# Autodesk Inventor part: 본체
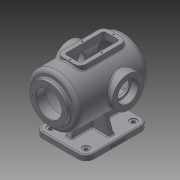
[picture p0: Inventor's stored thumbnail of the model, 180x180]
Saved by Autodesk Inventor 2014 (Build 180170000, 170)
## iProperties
Created: 2021-11
Part Number: 본체
Material: 일반
Document SubType Name: Modeling
Designer: kb542-02
Density: 1 g/cm^3
Appearance: 기본값
Mass: 1311.57 g
Surface Area: 2406 cm^2
Volume: 1311.57 cm^3
Author: kb542-02
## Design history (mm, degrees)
sketch "스케치1"
  geometry: L1 (0, 0)-(210, 0); L2 (0, 32.5)-(0, 47.5); L3 (0, 47.5)-(10, 47.5); L4 (10, 47.5)-(10, 65); L5 (10, 65)-(185.993, 65); L6 (0, 32.5)-(25, 32.5); L7 (25, 32.5)-(25, 55); L8 (25, 55)-(181.239, 55); L9 (200, 0)-(210, 0); A1 r 100 centre (110, 0) between (210, 0) and (185.993, 65); A2 r 90 centre (110, 0) between (200, 0) and (181.239, 55)
  constraints: 18 end point, 4 point on circle, 3 parallel, 3 perpendicular, 2 centre point, 2 horizontal, 1 coincident, 1 collinear, 1 horizontal alignment, 1 point on line, 1 vertical alignment
  dimensions: "d0" = 100 radius of A1; "d1" = 65 diameter of L6 L1; "d2" = 95 diameter of L3 L1; "d3" = 130 diameter of L5 L1; "d4" = 110 diameter of L8 L1; "d5" = 210 distance from line of L1.end L2; "d7" = 25 distance between parallel lines of L7 L2; "d8" = 10 radial gap between concentric circles of A1 A2; "d137" = 10 distance between parallel lines of L4 L2
revolve "회전1" sketch "스케치1" stored, may be unused: angle "d6" = 90 deg
node "작업 평면1"
sketch "스케치2"
  geometry: L1 (30, 65)-(190, 65); L2 (190, 65)-(190, -65); L3 (190, -65)-(30, -65); L4 (30, -65)-(30, 65); L5 (0, -47.5)-(0, 47.5) reference; 3 further points
  constraints: 8 end point, 2 midpoint, 2 parallel, 1 horizontal, 1 horizontal alignment, 1 perpendicular
  dimensions: "d10" = 130 distance between parallel lines of L3 L1; "d11" = 160 distance between parallel lines of L4 L2; "d12" = 30 distance between parallel lines of L5 L4
extrude "돌출1" join sketch "스케치2" distance "d13" = 14; taper "d14" = 0 deg
fillet "모깎기1" dims "d15" = 20
sketch "스케치3"
  geometry: A1 r 20 centre (170, 45) between (190, 45) and (170, 65) reference; A2 r 20 centre (50, 45) between (50, 65) and (30, 45) reference; A3 r 20 centre (50, -45) between (30, -45) and (50, -65) reference; A4 r 20 centre (170, -45) between (170, -65) and (190, -45) reference; 5 further points
  constraints: 4 coincident
hole "구멍1" sketch "스케치3" at (50, 45), (170, 45), (170, -45), (50, -45) diameter "d16" = 9; stored, may be unused: countersink angle "d20" = 90 deg, drill point angle "d22" = 118 deg; dims "d17" = 6, "d18" = 18, "d19" = 2, "d21" = 8
sketch "스케치4"
  geometry: L1 (170, 65)-(50, 65) reference; L2 (190, -45)-(190, 45) reference; L3 (103, 50)-(117, 50); L4 (117, 50)-(117, -50); L5 (117, -50)-(103, -50); L6 (103, -50)-(103, 50); L7 (50, 7)-(170, 7); L8 (170, 7)-(170, -7); L9 (170, -7)-(50, -7); L10 (50, -7)-(50, 7); 7 further points
  constraints: 16 end point, 6 midpoint, 4 parallel, 2 horizontal, 2 horizontal alignment, 2 perpendicular, 2 vertical alignment
  dimensions: "d23" = 14 distance between parallel lines of L4 L6; "d24" = 14 distance between parallel lines of L9 L7; "d25" = 120 distance between parallel lines of L8 L10; "d26" = 100 distance between parallel lines of L5 L3
extrude "돌출3" join sketch "스케치4" stored distance "d29" = 14; taper "d30" = 0 deg
feature "면 기울기1" dims angle "d31" = 20 deg
sketch "스케치8" dims "d60" = 80
  geometry: L1 (0, 0)-(0, 40); C1 r 47.5 at (0, 0) reference; 1 further point
  constraints: 2 coincident, 2 end point, 1 vertical, 1 vertical alignment, 2 other
hole "구멍4" sketch "스케치8" at (0, 40) diameter "d61" = 3.242; stored, may be unused: countersink angle "d65" = 90 deg, drill point angle "d67" = 118 deg; dims "d62" = 11, "d63" = 52, "d64" = 18, "d66" = 13
node "작업 평면3"
sketch "스케치9"
  geometry: L1 (50, 30)-(170, 30); L2 (170, 30)-(170, -30); L3 (170, -30)-(50, -30); L4 (50, -30)-(50, 30); L5 (0, -47.5)-(0, 47.5) reference; 3 further points
  constraints: 8 end point, 2 midpoint, 2 parallel, 1 horizontal, 1 horizontal alignment, 1 perpendicular
  dimensions: "d72" = 50 distance between parallel lines of L5 L4; "d73" = 120 distance between parallel lines of L2 L4; "d74" = 60 distance between parallel lines of L3 L1
extrude "돌출5" join sketch "스케치9" stored distance "d75" = 150; taper "d76" = 0 deg
fillet "모깎기2" dims "d77" = 15
sketch "스케치10"
  geometry: L1 (170, 15)-(170, -15) reference; L2 (65, 30)-(155, 30) reference; L3 (50, -15)-(50, 15) reference; L4 (155, -30)-(65, -30) reference; L5 (160, 15)-(160, -15); L6 (155, -20)-(65, -20); L7 (60, -15)-(60, 15); L8 (65, 20)-(155, 20); A1 r 15 centre (155, -15) between (155, -30) and (170, -15) reference; A2 r 15 centre (155, 15) between (170, 15) and (155, 30) reference; A3 r 15 centre (65, 15) between (65, 30) and (50, 15) reference; A4 r 15 centre (65, -15) between (50, -15) and (65, -30) reference; A5 r 5 centre (155, 15) between (160, 15) and (155, 20); A6 r 5 centre (155, -15) between (155, -20) and (160, -15); A7 r 5 centre (65, -15) between (60, -15) and (65, -20); A8 r 5 centre (65, 15) between (65, 20) and (60, 15); 1 further point
  constraints: 8 end point, 8 point on circle, 4 centre point, 7 other
  dimensions: "d78" = 10 distance between parallel lines of L2 L8
extrude "돌출6" cut sketch "스케치10" stored distance "d79" = 150; taper "d80" = 0 deg
sketch "스케치11"
  geometry: L1 (127, 75)-(127, -75); L2 (110, 25)-(110, -25); 5 further points
  constraints: 4 end point, 4 horizontal alignment, 2 midpoint, 1 parallel, 1 vertical alignment
  dimensions: "d81" = 55 horizontal distance of point (165, 0) L2.start; "d82" = 55 horizontal distance of point (55, 0) L2.start; "d83" = 17 distance from line of L2.start L1; "d84" = 50 distance of L2.end L2.start; "d118" = 150 distance of L1.start L1.end
hole "구멍5" sketch "스케치11" at (110, 25), (110, -25), (165, 0), (55, 0) diameter "d85" = 3.242; stored, may be unused: countersink angle "d89" = 90 deg, drill point angle "d91" = 118 deg; dims "d86" = 9, "d87" = 52, "d88" = 18, "d90" = 11
node "작업 평면4"
sketch "스케치12"
  geometry: L1 (0, -47.5)-(0, 47.5) reference; C1 r 40 at (127, 0); 1 further point
  constraints: 1 centre point, 1 horizontal alignment
  dimensions: "d93" = 80 diameter of C1; "d94" = 127 distance from line of L1 C1.centre
extrude "돌출7" join sketch "스케치12" stored distance "d95" = 150; taper "d96" = 0 deg
sketch "스케치13" dims "d97" = 65
  geometry: L1 (0, 0)-(0, 32.5); C1 r 40 at (0, 0) reference; 2 further points
  constraints: 2 coincident, 2 end point, 1 vertical, 1 vertical alignment, 2 other
hole "구멍6" sketch "스케치13" at (0, 32.5) diameter "d98" = 3.242; stored, may be unused: countersink angle "d102" = 90 deg, drill point angle "d104" = 118 deg; dims "d99" = 11, "d100" = 52, "d101" = 18, "d103" = 13
fillet "모깎기3" dims "d111" = 3, "d112" = 10
fillet "모깎기4" dims "d113" = 3
fillet "모깎기5" dims "d114" = 3
node "작업 평면5"
sketch "스케치16"
  geometry: L1 (120, 0)-(0, 0) reference; 3 further points
  constraints: 1 midpoint, 1 vertical alignment, 1 other
  dimensions: "d120" = 5 distance of point (60, 0) point (60, 5)
feature "엠보싱1" sketch "스케치16" dims "d0" = 100, "d1" = 65, "d2" = 95, "d3" = 130, "d4" = 110, "d5" = 210, "d7" = 25, "d8" = 10, "d10" = 130, "d11" = 160, "d12" = 30, "d121" = 0.5, "d122" = 0, "d137" = 10
hole "구멍7" diameter "d125" = 42; stored, may be unused: countersink angle "d129" = 90 deg, drill point angle "d131" = 118 deg; dims "d123" = 10, "d124" = 10, "d126" = 11, "d127" = 52, "d128" = 18, "d130" = 40
fillet "모깎기6" dims "d132" = 3
fillet "모깎기7" dims "d133" = 0.3
chamfer "모따기2" distance "d134" = 1; stored, may be unused: second distance "d135" = 2, angle "d136" = 45 deg
node "솔리드1"
pattern_circular "원형 패턴2" dims angle "d69" = 360 deg
pattern_circular "원형 패턴3" dims angle "d106" = 360 deg
mirror "대칭3"
mirror "대칭4"
other parameters: "d9" = -114, "d92" = -75, "d119" = 27.25
